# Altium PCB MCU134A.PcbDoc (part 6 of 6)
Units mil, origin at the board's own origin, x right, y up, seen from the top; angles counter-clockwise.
Board outline 4163.98 x 2693.8 mil, 6 copper layers (Top Layer, GND1, SIG1, PWR, GND2, Bottom), stack 58.132 mil thick; 218 components, 287 nets, 1260 pads, 770 vias.
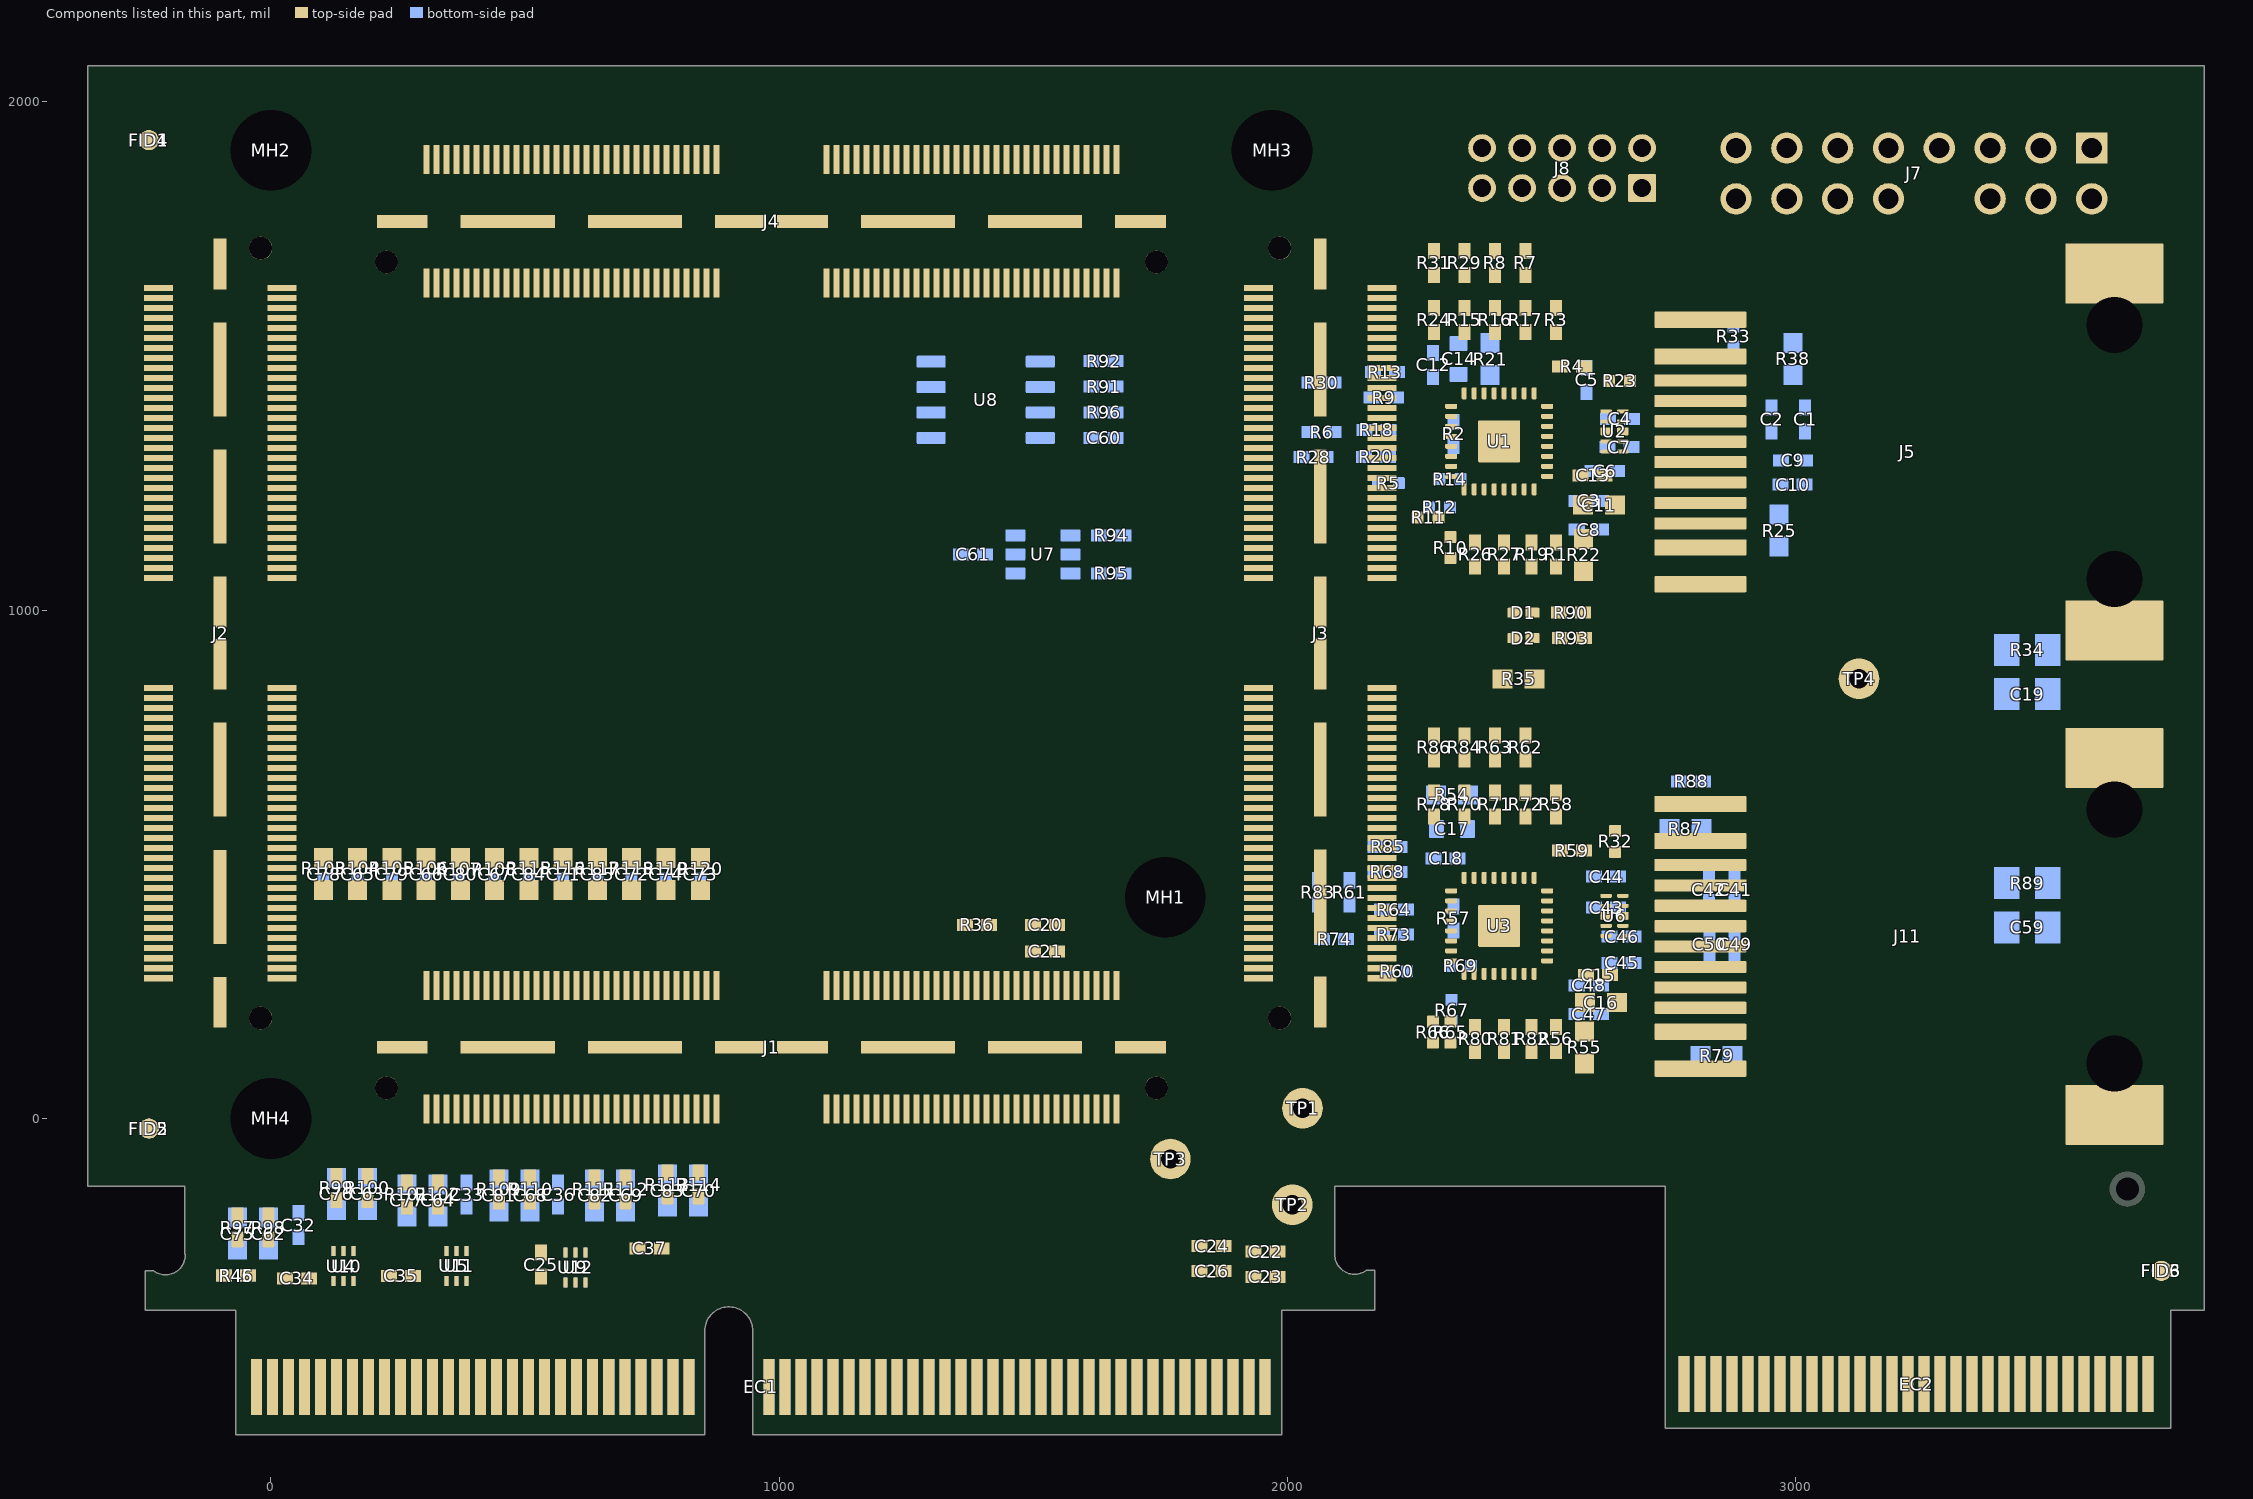
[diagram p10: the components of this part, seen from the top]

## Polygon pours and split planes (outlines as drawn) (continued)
5V0_IN on PWR "PWR Layer 4-5V0_IN" (solid, remove dead copper, pour order 23): 760,-400.85 715.85,-445 695,-445 685,-435 635,-435 591,-391 591,-154.38 760.38,15 1000,15 1370,15 1450,95 1450,330.1 1310,468.73 1310,690 1390,770 1990,770 2070,690 2070,216 2213,73 2857.64,73 2970,-39.36 2970,-136 3133.97,-299.97 3685.16,-299.97 3711.31,-326.12 3711.31,-530 3661.31,-580 2858.16,-580 2777,-498.84 2777,-129 2761,-113 2091.84,-113 2040,-164.84 2003.7,-201.14 1790,-201.14 1790,-310.47 1835,-355.47 1835,-378.34 1860,-403.34 1860,-435.36 1845.36,-450 1830.23,-450 1826.97,-446.74 1826.97,-428.5 1825.6,-427.13 1774.51,-376.04 1643.15,-376.04 1634.53,-384.66 1634.53,-410.03 1638.08,-413.58 1638.08,-444.96 1632.45,-450.59 1613.94,-450.59 1605.95,-442.6 1605.95,-397.93 1567.83,-359.81 1436.23,-359.81 1420,-376.04 1420,-423.25 1403.12,-440.13 1391.05,-440.13 1379.78,-428.86 1379.78,-369.78 1367.25,-357.25 1107.25,-357.25 970,-220 840,-220 760,-300
3V3_OUT on PWR "NONET_L08_P-001" (solid, remove dead copper, pour order 97): 2461.72,1957.28 2429.72,1925.28 2429.72,1885.28 2413.25,1868.8 2373.25,1868.8 2319.93,1815.48 2319.93,1468.48 2245.72,1394.28 1875.72,1394.28 1796.76,1473.24 1700.25,1569.75 1202.2,1569.75 1136.72,1504.28 1136.72,1012.28 1211.72,939.59 2391.13,939.59 2435.06,895.67 2435.06,834.94 2250.39,834.94 2213.59,798.14 1393.59,798.14 1302.27,706.82 1302.27,501.73 1374.72,429.28 1423.52,429.28 1446.58,406.22 1446.58,301.13 1435.55,290.1 1278.95,290.1 772.97,796.08 141.93,796.08 14.72,668.87 14.72,249.28 44.72,219.28 47.22,211.78 57.22,211.78 74.72,194.28 74.72,-89.46 46.91,-117.27 46.91,-210.92 47.11,-210.72 74.72,-210.72 99.72,-235.72 99.72,-270.72 114.72,-285.72 294.72,-285.72 334.72,-245.72 334.72,-177.41 541.41,-177.41 579.72,-215.72 579.72,-395.72 578.1,-395.72 618.1,-435.72 682.56,-435.72 698.42,-451.58 724.25,-451.58 738.64,-437.19 778.85,-396.97 778.85,-313.59 856.72,-235.72 964.72,-235.72 1107.27,-378.27 1302.27,-378.27 1382.55,-458.54 1866.42,-458.54 1875.54,-449.43 1875.54,-361.54 1819.72,-305.72 1819.72,-240.72 1925.75,-134.7 2022.45,-134.7 2098.57,-210.81 2098.57,-316.88 2060.3,-355.15 1984.21,-355.15 1969.72,-369.63 1969.72,-535.72 1954.72,-550.72 1029.72,-550.72 984.72,-505.72 984.72,-400.72 984.23,-400.72 936.59,-353.09 867.36,-353.09 839.72,-380.72 839.72,-535.72 819.72,-555.72 74.72,-555.72 -35.28,-445.72 -35.28,-340.72 -135.28,-240.72 -135.28,-125.72 -280.28,19.28 -280.28,479.28 -277.35,482.2 -277.35,1252.2 -180.28,1349.28 144.72,1349.28 144.72,1359.28 574.72,1789.28 1616.72,1789.28 1849.86,2022.41 3667.59,2022.41 3724.7,1965.3 3724.7,1791.7 3708,1775 3532,1775 3532,1877 3453.24,1955.76 2592.72,1955.76
3V3_ETH on PWR "NONET_L08_P-001" (solid, remove dead copper, pour order 130): 2338.95,1696.2 2365.76,1723 2577,1723 2770,1530 2770,1400 2769.97,1310 2769.97,269.97 2650,150 2650,90 2640,80 2600,80 2590,90 2590,113 2578,125 2310,125 2098.47,336.53 2098.47,581.82 2336.64,820 2459.97,820 2469.97,830 2469.97,936.03 2425.48,980.52 1245.38,980.52 1169.97,1055.93 1169.97,1478.72 1237.28,1546.03 1675.32,1546.03 1851.35,1370 2244,1370 2338.95,1464
SHLD_GND on PWR "NONET_L08_P-001" (solid, remove dead copper, pour order 22): 3604,-188 3778,-188 3778,1725 3766.97,1736.03 3489.97,1736.03 3475.97,1722.03 3475.97,78.17 3524.01,30.12 3524.01,-108.01
GND on GND2 "GND2-GND" (solid, remove dead copper, pour order 129): 853.8,-555.16 853.8,-370.14 869.97,-353.97 929.97,-353.97 948.29,-372.29 948.29,-555.16 1989.23,-555.16 1989.23,-377.97 2171.95,-377.97 2171.95,-298.97 2155.96,-298.97 2146.2,-308.73 2119.1,-308.73 2092.95,-282.58 2092.95,-133.97 2743.26,-133.97 2743.26,-555.16 3738.54,-555.16 3738.54,-377.87 3803.95,-377.87 3803.95,2070.99 3803.94,2070.98 -360.03,2070.98 -360.02,2070.97 -360.02,-133.97 -169.05,-133.97 -168.55,-134.47 -168.55,-283.07 -191.19,-305.72 -225.3,-305.72 -231.05,-299.97 -247.05,-299.97 -247.05,-377.97 -70.05,-377.97 -70.05,-555.16 691.31,-555.16
SHLD_GND on GND2 "NONET_L08_P-001" (solid, remove dead copper, pour order 120): 3604,-188 3778,-188 3778,1725 3766.97,1736.03 3489.97,1736.03 3475.97,1722.03 3475.97,78.17 3524.01,30.12 3524.01,-108.01
GND on GND1 "GND2-GND" (solid, remove dead copper, pour order 134): 853.8,-555.16 853.8,-370.14 869.97,-353.97 929.97,-353.97 948.29,-372.29 948.29,-555.16 1989.23,-555.16 1989.23,-377.97 2171.95,-377.97 2171.95,-298.97 2155.96,-298.97 2146.2,-308.73 2119.1,-308.73 2092.95,-282.58 2092.95,-133.97 2743.26,-133.97 2743.26,-555.16 3738.54,-555.16 3738.54,-377.87 3803.95,-377.87 3803.95,2070.99 3803.94,2070.98 -360.03,2070.98 -360.02,2070.97 -360.02,-133.97 -169.05,-133.97 -168.55,-134.47 -168.55,-283.07 -191.19,-305.72 -225.3,-305.72 -231.05,-299.97 -247.05,-299.97 -247.05,-377.97 -70.05,-377.97 -70.05,-555.16 691.31,-555.16
SHLD_GND on GND1 "NONET_L08_P-001" (solid, remove dead copper, pour order 133): 3604,-188 3778,-188 3778,1725 3766.97,1736.03 3489.97,1736.03 3475.97,1722.03 3475.97,78.17 3524.01,30.12 3524.01,-108.01
GND on SIG1 "SIG1-GND" (solid, remove dead copper, pour order 135): 853.8,-555.16 853.8,-370.14 869.97,-353.97 929.97,-353.97 948.29,-372.29 948.29,-555.16 1989.23,-555.16 1989.23,-377.97 2171.95,-377.97 2171.95,-298.97 2155.96,-298.97 2146.2,-308.73 2119.1,-308.73 2092.95,-282.58 2092.95,-133.97 2743.26,-133.97 2743.26,-555.16 3738.54,-555.16 3738.54,-377.87 3803.95,-377.87 3803.95,2070.99 3803.94,2070.98 -360.03,2070.98 -360.02,2070.97 -360.02,-133.97 -169.05,-133.97 -168.55,-134.47 -168.55,-283.07 -191.19,-305.72 -225.3,-305.72 -231.05,-299.97 -247.05,-299.97 -247.05,-377.97 -70.05,-377.97 -70.05,-555.16 691.31,-555.16
SHLD_GND on SIG1 "NONET_L08_P-001" (solid, remove dead copper, pour order 131): 3604,-188 3778,-188 3778,1725 3766.97,1736.03 3489.97,1736.03 3475.97,1722.03 3475.97,78.17 3524.01,30.12 3524.01,-108.01

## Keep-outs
Top Layer:
  lines w0.5: 74,44 74,569.95 113.05,609 831.73,609 899,541.73 899,471 899,452 895,448 781,334 762,334 733,305 714.53,305 713.05,305 709.41,301.35 709.41,301.16 709.41,232.63 709.41,221.5 709.41,-12.57 714.84,-18 715.36,-18 801.61,-18 879.89,-96.28 935.28,-96.28 959,-120 959,-163.05 740.37,-381.69 731.67,-390.39 729.29,-392.76 ; 802.89,-19.28 809.14,-25.53
SIG1:
  lines w0.5: 74,44 74,558 125,609 821,609 899,531 899,471 899,452 895,448 781,334 762,334 733,305 714.53,305 713.05,305 709.41,301.35 709.41,301.16 709.41,232.63 709.41,221.5 709.41,-12.57 714.84,-18 715.36,-18 801.61,-18 879.89,-96.28 935.28,-96.28 959,-120 959,-163.05 729.29,-392.76 ; 802.89,-19.28 809.14,-25.53
GND1:
  lines w0.5: 74,44 74,558 125,609 821,609 899,531 899,471 899,452 895,448 781,334 762,334 733,305 714.53,305 713.05,305 709.41,301.35 709.41,301.16 709.41,232.63 709.41,221.5 709.41,-12.57 714.84,-18 715.36,-18 801.61,-18 879.89,-96.28 935.28,-96.28 959,-120 959,-163.05 729.29,-392.76 ; 802.89,-19.28 809.14,-25.53
GND2:
  lines w0.5: 74,44 74,558 125,609 821,609 899,531 899,471 899,452 895,448 781,334 762,334 733,305 714.53,305 713.05,305 709.41,301.35 709.41,301.16 709.41,232.63 709.41,221.5 709.41,-12.57 714.84,-18 715.36,-18 801.61,-18 879.89,-96.28 935.28,-96.28 959,-120 959,-163.05 729.29,-392.76 ; 802.89,-19.28 809.14,-25.53
PWR:
  lines w0.5: 74,44 74,558 125,609 821,609 899,531 899,471 899,452 895,448 781,334 762,334 733,305 714.53,305 713.05,305 709.41,301.35 709.41,301.16 709.41,232.63 709.41,221.5 709.41,-12.57
Bottom:
  lines w0.5: 74,44 74,568.63 121.43,616.06 824.84,616.06 899,541.91 899,471 899,452 895,448 781,334 711.72,264.72 711.72,-10.9 718.81,-18 801.61,-18 879.89,-96.28 935.28,-96.28 959,-120 959,-163.05 729.29,-392.76 ; 802.89,-19.28 809.14,-25.53
Keep-Out Layer:
  circle w4: c1742.48,1685.08 r40
  circle w4: c-20.08,1712.48 r40
  circle w4: c1760,435 r120
  circle w4: c1970,1905 r120
  circle w4: c0,1905 r120
  circle w4: c-20.08,197.52 r40
  circle w4: c227.52,1685.08 r40
  circle w4: c1985.08,1712.48 r40
  circle w4: c1985.08,197.52 r40
  circle w4: c1742.48,60.08 r40
  circle w4: c227.52,60.08 r40
  text ".Layer_Name" at -423.89,-2614.75 h60

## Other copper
Top Layer:
  text ".Layer_Name" at -423.89,-2614.75 h60
SIG1:
  text ".Layer_Name" at -340,-2596 h60
GND1:
  text ".Layer_Name" at -258.03,-2598.97 h60
GND2:
  text ".Layer_Name" at -258.03,-2598.97 h60
PWR:
  text ".Layer_Name" at -232,-2649 h60
Bottom:
  text ".Layer_Name" at -348.89,-2605.75 h60

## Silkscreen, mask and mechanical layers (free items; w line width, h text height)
Top Overlay:
  lines w6: 2535,268 2535,261 ; 2547,290 2540,290 2535,290 2535,261 ; 2632,921 2632,820 2645,820 ; 2727.87,700 2685,700 2589,700 2589,626 2557,626 ; 2730,774 2730,675 2951,675 ; 2818,820 2645,820 ; 3225,1070 2925,1070 2925,1015 2710,1015 2700,1015 2700,1055 2630,1055 ; 3640,-185 3640,-245 ; 2505,725 2515,715 2515,735 2505,725 ; 2505,725 2560,725 2645,725 2645,790 2645,820 ; 2535,261 2542,268 2543,268 2526,268 2533,261 2535,261 ; 2557,626 2567,636 2567,616 2557,626 ; 2630,1055 2640,1045 2640,1065 2630,1055 ; 3640,-245 3630,-235 3650,-235 3640,-245
  lines w10: 107,327.84 112.16,333
  lines w20: 107,327.84 107,-5.24 125.92,-24.16 1791.84,-24.16 1805,-11 1805,264 1740,329 1588,329 ; 112.16,333 165,333 1376,333
  text "Emulation Connector" at 3073.63,1734.38 h55
  text "P1" at 2792,1692 h55
  text "ECAT1" at 2865.28,1686.1 h55
  text "PHY1" at 2285,1280 h55 r90
  text "PHY0" at 2280,325 h55 r90
  text "ECAT0" at 3030,-145 h55
  text "P0" at 2925,-150 h55
  text "SHLD_GND" at 3405,-300 h55
  text ".Layer_Name" at -423.89,-2619.76 h60
Bottom Overlay:
  rectangle: 69.44,693.8 757.88,792.03
  rectangle: 114.44,833.8 802.88,932.03
  lines w6: 2268,410 2281,410 2281,444 ; 2281,444 2275,438 2289,438 2283,444 2281,444
  lines w10: 891.32,811.8 891.32,910.03 ; 936.32,951.8 936.32,1050.03 ; 1074.62,1051.94 248.44,1051.94 248.44,951.94 1074.62,951.94 1074.62,1052.09 ; 203.44,811.94 1117,811.94 1117,911.94 203.44,911.94 203.44,811.94
  text "FSI Header" at 2637,1974 h55
  text "TMS" at 3470,1955 h55 r270
  text "3V3" at 3567,1954 h55 r270
  text "SDA" at 3066,1951 h55 r270
  text "GND" at 3270,1951 h55 r270
  text "TDI" at 3363,1951 h55 r270
  text "RX" at 3166,1947 h55 r270
  text "CLK" at 2960,1946 h55 r270
  text "POCI" at 2863,1944 h55 r270
  text "TX" at 3170,1697 h55 r270
  text "PTE" at 2859,1677 h55 r270
  text "SCL" at 3073,1674 h55 r270
  text "TCK" at 3468,1671 h55 r270
  text "TDO" at 3361,1670 h55 r270
  text "GND" at 3567,1665 h55 r270
  text "POCI" at 2964,1653 h55 r270
  text "MCU134A" at 780,1510 h90
  text "HSEC180ADAPEVM" at 995,1390 h90
  text "SL#" at 1059.21,980.3 h70
  text "TP4" at 3084,919 h55
  text "GND" at 3060,845 h55
  text "ASSY#" at 1107,842 h70
  text "MCU134A-001" at 796.67,831.57 h90
  text "TP1" at 2105,78 h55
  text "5V0" at 1980,66 h55
  text "TP2" at 2072,-107 h55
  text "3V3" at 1969,-121 h55
  text "TP3" at 1704,-134 h55
  text "5V0_OUT_CAN" at 1890,-190 h55
  text ".Layer_Name" at 2051,-2648 h60
Top Paste:
  text ".Layer_Name" at -423.89,-2619.76 h60
Bottom Paste:
  text ".Layer_Name" at -416.89,-2615.75 h60
Top Solder:
  lines w1: 1418.82,1755.59 1531.03,1755.59
  lines w50: -70.05,-377.97 -70.05,-613.97 852.06,-613.97 852.06,-416.97 cw(c899.06,-416.97) 946.06,-416.97 946.06,-613.97 1994.95,-613.97 1994.95,-377.97 ; 2743.26,-453.09 2743.26,-609.97 3738.54,-609.97 3738.54,-377.87
  text ".Layer_Name" at -423.89,-2619.76 h60
  text ".Layer_Name" at -423.89,-2619.76 h60
Bottom Solder:
  lines w50: -70.05,-377.97 -70.05,-613.97 852.06,-613.97 852.06,-416.97 cw(c899.06,-416.97) 946.06,-416.97 946.06,-613.97 1994.95,-613.97 1994.95,-377.97 ; 2743.26,-453.09 2743.26,-609.97 3738.54,-609.97 3738.54,-377.87
  text ".Layer_Name" at 2148,-2670 h60
Drill Guide:
  text ".Layer_Name" at -423.89,-2614.75 h60
M1 Board Outline:
  lines w10: -169.05,-266.97 -169.05,-133.97 -360.02,-133.97 -360.03,2070.98 1606.27,2070.98 3803.95,2070.99 3803.95,-377.87 3738.54,-377.87 3738.54,-609.97 2743.26,-609.97 2743.26,-133.97 2092.95,-133.97 2092.95,-170.38 2092.95,-267.97 ; -168.55,-266.95 cw(c-207.5,-268.88) -231.05,-299.97 -247.05,-299.97 -247.05,-377.97 -68.64,-377.97 -68.64,-386.59 ; 1989.23,-386.59 1989.23,-377.97 1994.95,-377.97 2171.95,-377.97 2171.95,-298.97 2155.95,-298.97 cw(c2132.45,-267.85) 2093.45,-267.97
  text ".Layer_Name" at -430,-2560 h60
M2 Board Dimensions:
  lines w10: 5007.95,974.01 5075.95,974.01 ; 5049.95,945.01 5076.95,973.01 ; 5049.95,1004.01 5076.95,974.01 ; 5083.95,2319.01 5151.95,2401.01 ; 5085.95,927.01 5085.95,1249.01 ; 5085.95,1290.01 5135.95,1236.01 5245.95,1236.01 5292.95,1293.01 ; 5085.95,1292.01 5085.95,2322.01 ; 5150.95,2402.01 5214.95,2315.01 ; 5168.95,1142.01 5236.95,1142.01 ; 5210.95,1113.01 5237.95,1141.01 ; 5210.95,1172.01 5237.95,1142.01 ; 5215.95,2314.01 5287.95,2404.01 ; 5246.95,927.01 5246.95,1209.01 ; 5292.95,1292.01 5292.95,2322.01 5292.95,2407.01 ; 5293.95,927.01 5293.95,1249.01 ; 5299.92,1942.63 cw(c5243.95,1235.01) 5683.29,1792.54 ; 5301.8,1941.26 ccw(c5441.55,2175.92) 5352.67,1917.67 ; 5301.95,977.01 5328.95,947.01 ; 5301.95,978.01 5328.95,1006.01 ; 5301.95,1948.01 cw(c5334.4,1774.03) 5364.67,1948.4 ; 5303.95,978.01 5371.95,978.01 ; 5303.95,1141.01 5330.95,1111.01 ; 5303.95,1142.01 5330.95,1170.01 ; 5305.95,1142.01 5373.95,1142.01 ; 5319.95,1331.01 5782.95,1903.01 ; 5629.95,1807.01 ccw(c5767.48,2147.44) 5684.61,1789.75 ; 5647.2,1840.31 cw(c5530.34,1706.86) 5685.95,1792
  text "30" at 5488.95,1963.01 h60
  text "18MIL" at 5414.95,1114.01 h60
  text "62MIL" at 5407.95,950.01 h60
  text "GOLD FINGER" at 4926.95,713.01 h60
  text "SIDE VIEW" at 4980.95,600.01 h60
  text ".Layer_Name" at -423.89,-2614.75 h60
M3 3D STEP Top:
  text ".Layer_Name" at -423.89,-2619.76 h60
M4 3D STEP Bottom:
  text ".Layer_Name" at -416.89,-2615.75 h60
M5 Assembly Top:
  lines w4: -247.05,-338.97 -246.55,-338.47 2171.95,-338.47
  lines w10: -1292.89,-2691.43 5307.11,-2691.43 ; -1292.89,-2488.1 5309.11,-2488.1 ; -1292.89,-2284.76 -1292.89,-2894.76 2712.11,-2894.76 5309.11,-2894.76 5309.11,-2284.76 -1292.39,-2284.76 -1292.39,-2894.76 283.11,-2894.76 ; 1172.11,-2894.76 1172.11,-2284.76 ; 2439.11,-2488.1 2439.11,-2284.76 ; 3279.11,-2488.1 3279.11,-2284.76 ; 3901.11,-2901.26 3901.11,-2698.43
  text "ASSEMBLY VARIANT:" at 152.11,-2195.26 h60
  text ".VariantName" at 1188.11,-2195.26 h60
  text "PCB VIEWED FROM TOP SIDE" at -1229.39,-2416.93 h60
  text "BOARD #:" at 1247.11,-2416.93 h60
  text ".PRJ_Number" at 1792.61,-2416.93 h60
  text "REV:" at 2637.11,-2416.93 h60
  text ".PCB_Rev" at 2928.61,-2416.93 h60
  text "SVN REV:" at 3475.11,-2416.93 h60
  text ".VersionControl_RevNumber" at 3981.11,-2416.93 h60
  text ".TID" at -627.39,-2560.26 h60
  text "TID #:" at -1089,-2612 h60
  text "GENERATED    :" at -1170.89,-2765.59 h60
  text "PLOT NAME =" at -1229.39,-2825.6 h60
  text ".plot_File_Name" at -423.89,-2825.6 h60
  text ".Print_Date" at 2118.61,-2825.6 h60
  text ".Print_Time" at 2847.61,-2825.6 h60
  text "TEXAS INSTRUMENTS" at 4112.11,-2825.6 h60
M6 Assembly Bottom:
  lines w4: -247.05,-338.97 2171.95,-338.97 2171.95,-338.47
  lines w10: -1286.39,-2484.59 5315.61,-2484.59 ; -1284.39,-2687.92 5315.61,-2687.92 ; 121.61,-2897.76 121.61,-2694.92 ; 743.61,-2484.59 743.61,-2281.26 ; 1583.61,-2484.59 1583.61,-2281.26 ; 2850.61,-2891.26 2850.61,-2281.26 ; 3739.61,-2891.26 5315.11,-2891.26 5315.11,-2281.26 -1286.39,-2281.26 -1286.39,-2891.26 1310.61,-2891.26 5315.61,-2891.26 5315.61,-2281.26
  text "COMPONENTS MARKED 'DNP' SHOULD NOT BE POPULATED." at 5108.11,-2075.26 h60
  text ".VariantName" at 4064.11,-2191.26 h60
  text "ASSEMBLY VARIANT:" at 5103.11,-2191.26 h60
  text ".VersionControl_RevNumber" at 41.61,-2413.42 h60
  text "SVN REV:" at 547.61,-2413.42 h60
  text ".PCB_Rev" at 1094.11,-2413.42 h60
  text "REV:" at 1385.61,-2413.42 h60
  text ".PRJ_Number" at 2230.11,-2413.42 h60
  text "BOARD #:" at 2775.61,-2413.42 h60
  text "PCB VIEWED FROM BOTTOM SIDE" at 5252.11,-2413.42 h60
  text ".TID" at 2230.11,-2616.76 h60
  text "TID #:" at 2775.61,-2616.76 h60
  text "TEXAS INSTRUMENTS" at -89.39,-2822.09 h60
  text ".Print_Time" at 1175.11,-2822.09 h60
  text ".Print_Date" at 1904.11,-2822.09 h60
  text "GENERATED    :" at 2773.61,-2822.09 h60
  text ".plot_File_Name" at 4446.61,-2822.09 h60
  text "PLOT NAME =" at 5252.11,-2822.09 h60
M9 Title Sheet:
  drawing of 57 lines, arcs and shapes, not listed
  text "1" at -261.06,6280.24 h70
  text "2" at 2234.61,6280.24 h70
  text "3" at 4723.95,6280.24 h70
  text "4" at 7230.62,6280.24 h70
  text "5" at 9729.61,6280.24 h70
  text "6" at 12234.61,6280.24 h70
  text "A" at -1417.39,5137.24 h70
  text "A" at 13382.61,5137.24 h70
  text "B" at -1417.39,2757.24 h70
  text "B" at 13382.61,2757.24 h70
  text "C" at -1417.39,382.24 h70
  text "C" at 13382.61,382.24 h70
  text "PROJECT TITLE:" at 10342.61,-1478.76 h45
  text ".PRJ_Title" at 10392.61,-1612.08 h70
  text "DESIGNED FOR:" at 10342.61,-1779.76 h45
  text ".PRJ_Customer" at 10392.61,-1919.76 h70
  text "D" at -1417.39,-1987.76 h70
  text "D" at 13382.61,-1987.76 h70
  text "FILE NAME:" at 10342.61,-2079.76 h45
  text ".PCB_File_Name_No_Path" at 10392.61,-2199.76 h70
  text "Texas Instruments (TI) and/or its licensors do not warrant the accuracy or completeness of this specification" at 5373.11,-2361.6 h45
  text "ENGINEER:" at 10342.61,-2369.76 h45
  text "LAYOUT BY:" at 11847.61,-2369.76 h45
  text "or any information contained therein. TI and/or its licensors do not warrant that this design will meet" at 5328.12,-2474.26 h45
  text ".PRJ_Engineer" at 10392.61,-2524.75 h70
  text ".PCB_Layout" at 11898.11,-2524.75 h70
  text "the specifications, will be suitable for your application or fit for any particular purpose, or will operate in" at 5328.12,-2586.93 h45
  text ".Layer_Name" at -423.89,-2614.75 h60
  text "ALTIUM DESIGNER VERSION:" at 11847.61,-2679.76 h45
  text "an implementation. TI and/or its licensors do not warrant that the design is production worthy. You should" at 5328.12,-2699.59 h45
  text "completely validate and test your design implementation to confirm the system functionality for your application." at 5373.11,-2812.26 h45
  text ".print_Scale" at 10392.61,-2813.08 h70
  text ".Application_BuildNumber" at 11898.11,-2813.08 h70
  text "1" at -261.06,-3019.76 h70
  text "2" at 2234.61,-3019.76 h70
  text "3" at 4723.95,-3019.76 h70
  text "4" at 7230.62,-3019.76 h70
  text "5" at 9729.61,-3019.76 h70
  text "6" at 12234.61,-3019.76 h70
M10 Fab Notes:
  drawing of 182 lines, arcs and shapes, not listed
  text "J5 and J11: NPTH on SMT pads are intentional per manufacturers footprint.  SMT pad copper may be pulled back 5-8Mil from holes as needed for processing." at 7180,5027 h59
  text "DESIGN INFORMATION" at 11381.13,4739.92 h60
  text "4" at 11834.97,4611.03 h60
  text "MIN. TRACK WIDTH:" at 10736.57,4607.79 h60
  text "MIL" at 11987.57,4607.79 h60
  text "4.5" at 11785,4489 h60
  text "MIN. CLEARANCE:" at 10736.57,4483.66 h60
  text "MIL" at 11987.57,4483.66 h60
  text "MIN. VIA PAD SIZE:" at 10736.57,4359.54 h60
  text "18" at 11802.82,4359.54 h60
  text "MIL" at 11987.57,4359.54 h60
  text "0.05mm (2MIL)" at 11431.57,4229.64 h60
  text "MINIMUM ANNULAR RING" at 10407.34,4221.42 h60
  text "EXTERNAL" at 12139.57,4221.42 h60
  text "PER" at 10607.34,4111.29 h60
  text "IPC-D-275 CLASS 2 LEVEL C" at 10827.34,4111.29 h60
  text "MIL, HOLES" at 12315.57,4010.81 h60
  text "+/-" at 11923.11,4002.23 h60
  text "+/-" at 12777.11,4002.23 h60
  text "REGISTRATION TOLERANCES:" at 10407.34,4001.16 h60
  text "METAL" at 11607.11,4001.16 h60
  text "5" at 12183.31,4001.16 h60
  text "3" at 13016.31,4001.16 h60
  text "MIL" at 13132.57,4001.16 h60
  text "SCALE : NTS" at 240,3960 h80
  text "HOLE SIZE TOLERANCE (UNLESS OTHERWISE SPECIFIED):" at 10407.34,3902.85 h60
  text "+/-" at 12777.11,3899.97 h60
  text "3" at 13016.31,3898.91 h60
  text "MIL" at 13132.57,3898.91 h60
  text "NOTES:" at -960.66,3809.41 h60
  text "MATERIAL:" at 10332.57,3761.26 h60
  text "1. BOARD SHALL MEET THE REQUIREMENTS OF UL-796E WITH FLAMMABILITY RATING OF MINIMUM 94V-0. UL LOGO," at -933.91,3663.59 h60
  text "FR-4 High Tg" at 11319.01,3632.74 h60
  text "X" at 11174.57,3624.75 h60
  text "FR-408" at 10753.57,3620.23 h60
  text "OTHER" at 12241.57,3620.23 h60
  text "MANUFACTURER'S IDENTIFICATION AND DATE CODE LETTER SHALL BE RENDERED IN SILKSCREEN." at -827.18,3564.59 h60
  text "62 MIL (1.6mm) +/-10%" at 11073.67,3477.2 h60
  text "X" at 10953.57,3474.75 h60
  text "THICKNESS:" at 10407.34,3468.98 h60
  text "OTHER" at 12358.57,3468.98 h60
  text "2. VENDOR MAY ADJUST SOLDERMASK WHEREVER SOLDERMASK PADS ARE THE SAME SIZE (1:1) AS PER THE MANUFACTURING CAPABILITIES" at -940.9,3438.81 h60
  text "AND ALL OTHER SOLDER MASK PADS SHALL NOT BE MODIFIED, PROVIDED NO ADJACENT COPPER IS EXPOSED AND NO CONFLICT IS PRODUCED" at -834.17,3339.81 h60
  text "TOLERANCE:" at 10407.34,3330.67 h60
  text "X" at 11255.57,3330.67 h60
  text "ANSI IPC-6012 TYPE 3 CLASS 2" at 11433.58,3330.67 h60
  text "WITH ANY STATED \"VIA TENTING/COVERING\" REQUIREMENTS." at -834.17,3246.52 h60
  text "OTHER +/-" at 11433.57,3186.48 h60
  text "3. MANUFACTURER'S IDENTIFICATION,DATECODE LETTER SHALL BE SILKSCREENED ON SOLDER SIDE OF THE BOARD." at -937.22,3128.43 h60
  text "BOW & TWIST:" at 10407.34,3041.29 h60
  text "X" at 11255.57,3041.29 h60
  text "ANSI IPC-6012 TYPE 3 CLASS 2" at 11433.58,3041.29 h60
  text "4. LAYER TO LAYER REGISTRATION SHALL BE WITHIN +/-2 MIL." at -937.22,2959.33 h60
  text "OTHER +/-" at 11433.57,2894.59 h60
  text "5. REFER IMPEDANCE TABLE FOR IMPEDANCE CONTROL TRACES ON LAYER 1, 3 & 6." at -937.22,2793.46 h60
  text "DRILLING:" at 10332.57,2763.97 h60
  text "NC_DRILL FILES" at 12093.57,2658.78 h60
  text "REFERENCE:" at 10407.34,2654.85 h60
  text "X" at 11064.57,2654.75 h60
  text "AS SHOWN" at 11242.57,2654.85 h60
  text "X" at 11965.57,2654.85 h60
  text "6. ALL VIAS ARE TENTED ON BOTH SIDES UNLESS OTHERWISE SOLDER MASK OPENED IN GERBER." at -937.22,2633.31 h60
  text "OTHER" at 12391.57,2512.59 h60
  text "PTH COPPER THICKNESS:" at 10407.01,2509.07 h60
  text "X" at 11546.25,2509.07 h60
  text "20-30 um" at 11674.24,2509.07 h60
  text "BOARD FINISH:" at 10332.57,2361.47 h60
  text "SILKSCREEN:" at 10487.79,2251.34 h60
  text "X" at 11445.57,2251.34 h60
  text "TOP" at 11562.57,2251.34 h60
  text "X" at 11955.57,2251.34 h60
  text "BOTTOM" at 12073.57,2251.34 h60
  text "SILKSCREEN COLOR:" at 10487.79,2096.15 h60
  text "X" at 11444.57,2096.15 h60
  text "WHITE" at 11562.57,2096.15 h60
  text "OTHER" at 12073.57,2096.15 h60
  text "BLUE" at 12728.57,1962.71 h60
  text "GREEN" at 11693.57,1952.71 h60
  text "OTHER" at 12311.57,1952.71 h60
  text "X" at 11575,1950 h60
  text "SOLDER RESIST COLOR:" at 10487.79,1945.84 h60
  text "MATTE" at 11693.57,1798.45 h60
  text "SEMI-GLOSS" at 12311.11,1797.82 h60
  text "X" at 12163,1795 h60
  text "IMMERSION GOLD (ENIG)" at 11393.57,1625.68 h60
  text "ENEPIG" at 12731.11,1618.46 h60
  text "SURFACE FINISH:" at 10332.57,1617.46 h60
  text "X" at 11215.57,1617.46 h60
  text "IMM. TIN/SILVER OR EQUIV" at 10662.11,1480.15 h60
  text "HARD GOLD OVER NICKEL 30u/80u, ON EDGEFINGERS" at 11036.53,1327.14 h60
  text "X" at 10505.57,1317.46 h60
  text "OTHER" at 10683.57,1316.21 h60
  text "ARRAY/PANEL:" at 10332.57,1180.83 h60
  text "X" at 11212,1175 h60
  text "CUT AND TRIM PER M1 BOARD OUTLINE" at 11393.57,1172.61 h60
  text "N.C. ROUTE" at 11393.57,1036.64 h60
  text "V. SCORE" at 12259.57,1036.64 h60
  text "CERTIFICATION:" at 10332.57,907.52 h60
  text "MATERIALS AND WORKMANSHIP FOR ALL PCBS" at 11057.57,907.52 h60
  text "TO MEET OR EXCEED THE REQUIREMENTS OF:" at 11057.57,813.45 h60
  text "X" at 10693,685 h60
  text "ANSI IPC-A-600F CLASS ->" at 10823.07,684.82 h60
  text "X" at 12471.08,684.82 h60
  text "2" at 12581.07,684.82 h60
  text "1" at 12266.07,683.33 h60
  text "3" at 12935.07,683.33 h60
  text "X" at 11507.08,537.14 h60
  text "RoHS" at 11635.07,537.14 h60
  text "OTHER" at 12279.47,537.14 h60
  text "PER ORDER" at 12676.53,537.14 h60
  text "ALL BOARDS MUST MEET OR EXCEED UL94-V0 REQUIREMENTS." at 10360.11,383.31 h60
  text "PCB MUST BEAR THE UL94V-0 UL REGISTERED MATERIAL ID NUMBER" at 10360.11,267.25 h60
  text "ADDITIONAL REQUIREMENTS:" at 10332.57,97.82 h60
  text "REQUIRED" at 12114.57,-23.64 h60
  text "BARE BOARD ELEC. TEST:" at 10347.34,-26.49 h60
  text "NONE" at 11653.07,-26.49 h60
  text "X" at 12589.11,-26.26 h60
  text "PER ORDER" at 12706.57,-26.49 h60
  text "OUTER LAYERS 6 MIL WIDE, 6 MIL SPACE / TRACES REQUIRE 100 OHM DIFFERENTIAL IMPEDANCE" at 10584.18,-328.19 h60
  text "INNER LAYERS 5 MIL WIDE, 7 MIL SPACE / TRACES REQUIRE 100 OHM DIFFERENTIAL IMPEDANCE" at 10554.18,-513.19 h60
  text "OUTER LAYERS 6.1 MIL WIDE, 6 MIL SPACE / TRACES REQUIRE 90 OHM DIFFERENTIAL IMPEDANCE" at 10566.5,-699.04 h60
  text ".Layer_Name" at -423.89,-2614.75 h60
M11 Gerber Information:
  lines w10: -1292.89,-2686.42 5307.11,-2686.42 ; -1292.89,-2483.09 5309.11,-2483.09 ; -1292.89,-2279.76 -1292.89,-2889.76 2712.11,-2889.76 5309.11,-2889.76 5309.11,-2279.76 -1292.39,-2279.76 -1292.39,-2889.76 283.11,-2889.76 ; 1172.11,-2889.76 1172.11,-2279.76 ; 2439.11,-2483.09 2439.11,-2279.76 ; 3279.11,-2483.09 3279.11,-2279.76 ; 3901.11,-2896.26 3901.11,-2693.42
  text "ALL ARTWORK VIEWED FROM TOP SIDE" at -1229.39,-2411.92 h60
  text "BOARD #:" at 1247.11,-2411.92 h60
  text ".PRJ_Number" at 1792.61,-2411.92 h60
  text "REV:" at 2637.11,-2411.92 h60
  text ".PCB_Rev" at 2928.61,-2411.92 h60
  text "SVN REV:" at 3475.11,-2411.92 h60
  text ".VersionControl_RevNumber" at 3981.11,-2411.92 h60
  text "LAYER NAME =" at -1229.39,-2614.75 h60
  text "TID #:" at 1247.11,-2615.26 h60
  text ".TID" at 1792.61,-2615.26 h60
  text "PLOT NAME =" at -1229.39,-2820.59 h60
  text ".plot_File_Name" at -423.89,-2820.59 h60
  text "GENERATED    :" at 1249.11,-2820.59 h60
  text ".Print_Date" at 2118.61,-2820.59 h60
  text ".Print_Time" at 2847.61,-2820.59 h60
  text "TEXAS INSTRUMENTS" at 4112.11,-2820.59 h60
M12 Stackup:
  drawing of 466 lines, arcs and shapes, not listed
  text "6" at 7956.34,3176.61 h60
  text "IMPEDANCE TABLE :" at 6799.95,3161.23 h80
  text "LAYER" at 6340.22,2971.58 h70
  text "TRACE WIDTH" at 6627.42,2970.73 h70
  text "SPACING" at 7112.42,2970.73 h70
  text "IMPEDANCE +/- 10%" at 7447.42,2970.73 h70
  text "REFERENCE LAYER" at 8172.42,2970.73 h70
  text "-" at 7235,2800 h65
  text "5.66 MILS" at 6686.1,2794.75 h65
  text "LAYER-2 (GND LAYER)" at 8133.83,2794.75 h65
  text "TOP" at 6365,2785 h70
  text "50 OHM" at 7637,2785 h65
  text "LAYER-2 (GND LAYER)" at 8133.83,2612.55 h65
  text "4 MILS" at 6686.1,2607 h65
  text "7 MILS" at 7167,2606 h65
  text "TOP" at 6370,2595 h70
  text "100 OHM" at 7620,2592 h65
  text "LAYER-2 (GND LAYER)" at 8133.83,2426.55 h65
  text "5 MILS" at 6686.1,2425.86 h65
  text "90 OHM" at 7643,2421 h65
  text "TOP" at 6370,2420 h60
  text "6.22 MILS" at 7127,2420 h65
  text "6.66  MILS" at 6686.1,2236 h65
  text "50 OHM" at 7626,2236 h65
  text "L3" at 6395,2235 h60
  text "-" at 7240,2235 h65
  text "LAYER-2 / LAYER-4" at 8133.83,2226.55 h65
  text "4.2  MILS" at 6686.1,2062 h65
  text "L3" at 6385,2060 h60
  text "100 OHM" at 7612,2054 h65
  text "6 MILS" at 7158,2052 h65
  text "LAYER-2 / LAYER-4" at 8133.83,2051.55 h65
  text "-" at 7225,1895 h65
  text "LAYER-5(GND LAYER)" at 8133.83,1890 h65
  text "BOTTOM" at 6312.67,1877.48 h60
  text "5.66 MILS" at 6686.1,1876 h65
  text "50 OHM" at 7626,1869 h65
  text "LAYER-5(GND LAYER)" at 8133.83,1710 h65
  text "7 MILS" at 7152,1705 h65
  text "BOTTOM" at 6315.67,1701.48 h60
  text "4 MILS" at 6686.1,1702 h65
  text "100 OHM" at 7606,1696 h65
  text "LAYER-5(GND LAYER)" at 8133.83,1535 h65
  text "BOTTOM" at 6315.67,1530.25 h60
  text "6.22 MILS" at 7124.35,1530.86 h65
  text "90 OHM" at 7612,1528 h65
  text "5 MILS" at 6686.1,1527 h65
  text "Layer" at 5093.58,44 h60
  text "Name" at 5503.49,44 h60
  text "Material" at 6433.23,44 h60
  text "Thickness" at 7293,44 h60
  text "Constant" at 7942.84,44 h60
  text "Board Layer Stack" at 8512.7,44 h60
  text "Top Overlay" at 5503.49,-76 h60
  text "Top Solder" at 5503.49,-196 h60
  text "Solder Resist" at 6433.23,-196 h60
  text "2.00mil" at 7293,-196 h60
  text "3.6" at 7942.84,-196 h60
  text "1" at 5093.58,-316 h60
  text "Top Layer" at 5503.49,-316 h60
  text "1.85mil" at 7293,-316 h60
  text "Dielectric 1" at 5503.49,-436 h60
  text "FR-4" at 6433.23,-436 h60
  text "3.70mil" at 7293,-436 h60
  text "4.1" at 7942.84,-436 h60
  text "2" at 5093.58,-556 h60
  text "GND1" at 5503.49,-556 h60
  text "1.26mil" at 7293,-556 h60
  text "Dielectric 2" at 5503.49,-676 h60
  text "FR-4" at 6433.23,-676 h60
  text "5.00mil" at 7293,-676 h60
  text "3.7" at 7942.84,-676 h60
  text "3" at 5093.58,-796 h60
  text "SIG1" at 5503.49,-796 h60
  text "1.26mil" at 7293,-796 h60
  text "Dielectric 3" at 5503.49,-916 h60
  text "FR-4" at 6433.23,-916 h60
  text "32.00mil" at 7293,-916 h60
  text "3.7" at 7942.84,-916 h60
  text "4" at 5093.58,-1036 h60
  text "PWR" at 5503.49,-1036 h60
  text "1.26mil" at 7293,-1036 h60
  text "Dielectric 4" at 5503.49,-1156 h60
  text "FR-4" at 6433.23,-1156 h60
  text "5.00mil" at 7293,-1156 h60
  text "3.7" at 7942.84,-1156 h60
  text "5" at 5093.58,-1276 h60
  text "GND2" at 5503.49,-1276 h60
  text "1.26mil" at 7293,-1276 h60
  text "Dielectric 5" at 5503.49,-1396 h60
  text "FR-4" at 6433.23,-1396 h60
  text "3.70mil" at 7293,-1396 h60
  text "4.1" at 7942.84,-1396 h60
  text "6" at 5093.58,-1516 h60
  text "Bottom" at 5503.49,-1516 h60
  text "1.85mil" at 7293,-1516 h60
  text "Bottom Solder" at 5503.49,-1636 h60
  text "Solder Resist" at 6433.23,-1636 h60
  text "2.00mil" at 7293,-1636 h60
  text "3.6" at 7942.84,-1636 h60
  text "Bottom Overlay" at 5503.49,-1756 h60
  text ".Layer_Name" at -423.89,-2614.75 h60
M13 Component Bodies Top:
  text ".Layer_Name" at -423.89,-2619.76 h60
M14 Component Bodies Bottom:
  text ".Layer_Name" at -416.89,-2615.75 h60
M15 Courtyards Top:
  text ".Layer_Name" at -423.89,-2619.76 h60
M16 Courtyards Bottom:
  text ".Layer_Name" at -416.89,-2615.75 h60
Drill Drawing:
  circle w10: c-834.37,5176.83 r20
  circle w10: c-834.37,5176.83 r33.33
  lines w10: -867.71,4543.5 -867.71,4560.17 -851.04,4576.83 -867.71,4593.5 -867.71,4610.17 -851.04,4610.17 -834.37,4593.5 -817.71,4610.17 -801.04,4610.17 -801.04,4593.5 -817.71,4576.83 -801.04,4560.17 -801.04,4543.5 -817.71,4543.5 -834.37,4560.17 -851.04,4543.5 -867.71,4543.5 ; -867.71,4693.5 -834.37,4710.17 -801.04,4693.5 -817.71,4726.83 -801.04,4760.17 -834.37,4743.5 -867.71,4760.17 -851.04,4726.83 -867.71,4693.5 ; -867.71,4843.5 -801.04,4843.5 -801.04,4910.17 -867.71,4910.17 -867.71,4843.5 ; -867.71,4993.5 -801.04,4993.5 -801.04,5060.17 -867.71,5060.17 -867.71,4993.5 ; -867.71,5326.83 -834.37,5293.5 -801.04,5326.83 -834.37,5360.17 -867.71,5326.83 ; -867.71,5510.17 -801.04,5510.17 -834.37,5443.5 -867.71,5510.17 ; -867.71,5610.17 -851.04,5610.17 -851.04,5593.5 -817.71,5593.5 -817.71,5610.17 -801.04,5610.17 -801.04,5643.5 -817.71,5643.5 -817.71,5660.17 -851.04,5660.17 -851.04,5643.5 -867.71,5643.5 -867.71,5610.17 ; -867.71,5760.17 -851.04,5760.17 -834.37,5743.5 -817.71,5760.17 -801.04,5760.17 -817.71,5776.83 -801.04,5793.5 -817.71,5793.5 -834.37,5810.17 -851.04,5793.5 -867.71,5793.5 -851.04,5776.83 -867.71,5760.17 ; -854.37,5006.83 -814.37,5006.83 -814.37,5046.83 -854.37,5046.83 -854.37,5006.83
  lines w15: -927.5,4498.5 6804.33,4498.5 ; -927.5,5848.5 6804.33,5848.5 ; -376.62,4348.5 -376.62,5998.5 ; 213.22,4348.5 213.22,5998.5 ; 1362.88,4348.5 1362.88,5998.5 ; 1868.76,4348.5 1868.76,5998.5 ; 3202.37,4348.5 3202.37,5998.5 ; 4535.98,4348.5 4535.98,5998.5 ; 5401.73,4348.5 5401.73,5998.5 ; -927.5,4348.5 6804.33,4348.5 6804.33,5998.5 -927.5,5998.5 -927.5,4348.5
  text "Symbol" at -837.5,5893.5 h72
  text "Count" at -331.62,5893.5 h72
  text "Hole Size" at 258.22,5893.5 h72
  text "Plated" at 1407.88,5893.5 h72
  text "Hole Tolerance (+)" at 1913.76,5893.5 h72
  text "Hole Tolerance (-)" at 3247.37,5893.5 h72
  text "Hole Length" at 4580.98,5893.5 h72
  text "Routed Path Length" at 5446.73,5893.5 h72
  text "9" at -111.7,5743.5 h60
  text "7.87mil (0.200mm)" at 313.2,5743.5 h60
  text "PTH" at 1407.88,5743.5 h60
  text "3.00mil (0.076mm)" at 2060.71,5743.5 h60
  text "3.00mil (0.076mm)" at 3247.37,5743.5 h60
  text "-" at 4580.98,5743.5 h60
  text "-" at 5446.73,5743.5 h60
  text "761" at -161.68,5593.5 h60
  text "8.00mil (0.203mm)" at 313.2,5593.5 h60
  text "PTH" at 1407.88,5593.5 h60
  text "3.00mil (0.076mm)" at 2060.71,5593.5 h60
  text "3.00mil (0.076mm)" at 3247.37,5593.5 h60
  text "-" at 4580.98,5593.5 h60
  text "-" at 5446.73,5593.5 h60
  text "10" at -136.69,5443.5 h60
  text "35.04mil (0.890mm)" at 283.21,5443.5 h60
  text "PTH" at 1407.88,5443.5 h60
  text "3.00mil (0.076mm)" at 2060.71,5443.5 h60
  text "3.00mil (0.076mm)" at 3247.37,5443.5 h60
  text "-" at 4580.98,5443.5 h60
  text "-" at 5446.73,5443.5 h60
  text "4" at -111.7,5293.5 h60
  text "37.99mil (0.965mm)" at 283.21,5293.5 h60
  text "PTH" at 1407.88,5293.5 h60
  text "3.00mil (0.076mm)" at 2060.71,5293.5 h60
  text "3.00mil (0.076mm)" at 3247.37,5293.5 h60
  text "-" at 4580.98,5293.5 h60
  text "-" at 5446.73,5293.5 h60
  text "15" at -136.69,5143.5 h60
  text "40.16mil (1.020mm)" at 293.21,5143.5 h60
  text "PTH" at 1407.88,5143.5 h60
  text "3.00mil (0.076mm)" at 2060.71,5143.5 h60
  text "3.00mil (0.076mm)" at 3247.37,5143.5 h60
  text "-" at 4580.98,5143.5 h60
  text "-" at 5446.73,5143.5 h60
  text "1" at -101.7,4993.5 h60
  text "45.00mil (1.143mm)" at 293.21,4993.5 h60
  text "PTH" at 1407.88,4993.5 h60
  text "3.00mil (0.076mm)" at 2060.71,4993.5 h60
  text "3.00mil (0.076mm)" at 3247.37,4993.5 h60
  text "-" at 4580.98,4993.5 h60
  text "-" at 5446.73,4993.5 h60
  text "8" at -111.7,4843.5 h60
  text "45.28mil (1.150mm)" at 293.21,4843.5 h60
  text "NPTH" at 1407.88,4843.5 h60
  text "3.00mil (0.076mm)" at 2060.71,4843.5 h60
  text "3.00mil (0.076mm)" at 3247.37,4843.5 h60
  text "-" at 4580.98,4843.5 h60
  text "-" at 5446.73,4843.5 h60
  text "4" at -111.7,4693.5 h60
  text "110.24mil (2.800mm)" at 263.22,4693.5 h60
  text "NPTH" at 1407.88,4693.5 h60
  text "1.97mil (0.050mm)" at 2065.71,4693.5 h60
  text "1.18mil (0.030mm)" at 3247.37,4693.5 h60
  text "-" at 4580.98,4693.5 h60
  text "-" at 5446.73,4693.5 h60
  text "4" at -111.7,4543.5 h60
  text "159.00mil (4.039mm)" at 258.22,4543.5 h60
  text "NPTH" at 1407.88,4543.5 h60
  text "3.00mil (0.076mm)" at 2060.71,4543.5 h60
  text "3.00mil (0.076mm)" at 3247.37,4543.5 h60
  text "-" at 4580.98,4543.5 h60
  text "-" at 5446.73,4543.5 h60
  text "816 Total" at -331.62,4393.5 h60
  text ".Layer_Name" at -423.89,-2614.75 h60
M17 Embedded Cavity:
  text ".Layer_Name" at -423.89,-2614.75 h60
M18 Embedded Assembly:
  text ".Layer_Name" at -471,-2575 h60
M19 Embedded Keepout:
  text ".Layer_Name" at -427,-2583 h60
SOM_CONN:
  drawing of 2624 lines, arcs and shapes, not listed
  text "j4" at 980.05,1760 h40 r90
  text "j3" at 2131.28,879.25 h40 r90
  text "J2" at -132.27,868.64 h40 r90
  text "j1" at 972.22,148.68 h40 r90

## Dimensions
2132.45,-267.85 to 2244,-738 on M2 Board Dimensions
1994.95,-377.97 to 2171.95,-377.97 on M2 Board Dimensions
2743.26,-133.97 to 2092.95,-133.97 on M2 Board Dimensions
-360.03,-133.97 to -247.05,-377.97 on M2 Board Dimensions
899.06,-369.97 to 946.06,-613.97 on M2 Board Dimensions
-70.05,-377.97 to -70.05,-613.97 on M2 Board Dimensions
2743.26,-133.97 to 2743.26,-609.97 on M2 Board Dimensions
901.05,-418.09 to 750,-418.09 on M2 Board Dimensions
3738.54,-609.97 to 2743.26,-609.97 on M2 Board Dimensions
946.06,-613.97 to 1994.95,-613.97 on M2 Board Dimensions
852.06,-613.97 to -70.05,-613.97 on M2 Board Dimensions
852.06,-613.97 to 946.06,-613.97 on M2 Board Dimensions
3738.54,-377.87 to 3738.54,-609.97 on M2 Board Dimensions
-360.03,-133.97 to 3803.95,2070.99 on M2 Board Dimensions
3803.95,2070.99 to 3738.54,-609.97 on M2 Board Dimensions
